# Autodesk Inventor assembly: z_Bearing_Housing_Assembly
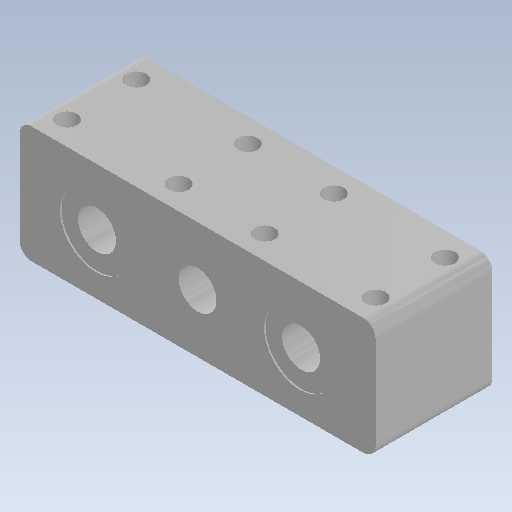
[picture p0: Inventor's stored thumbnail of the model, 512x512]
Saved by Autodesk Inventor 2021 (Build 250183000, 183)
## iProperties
Created: 2026-10
Part Number: z_Bearing_Housing_Assembly
Document SubType Name: Assembly
Designer: hp
Author: hp
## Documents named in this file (4)
- C:\Users\hp\Downloads\z_Bearing_Housing_Assembly.iam
- C:\Users\hp\Downloads\z_Bearing_Housing.ipt
- C:\Users\hp\Downloads\8mm_Bearing_2.ipt
- C:\Users\hp\Downloads\8mm_Bearing_3.ipt
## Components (3 placed, 2 different names)
1. z_Bearing_Housing:1
2. 8mm_Bearing:2
3. 8mm_Bearing:3
